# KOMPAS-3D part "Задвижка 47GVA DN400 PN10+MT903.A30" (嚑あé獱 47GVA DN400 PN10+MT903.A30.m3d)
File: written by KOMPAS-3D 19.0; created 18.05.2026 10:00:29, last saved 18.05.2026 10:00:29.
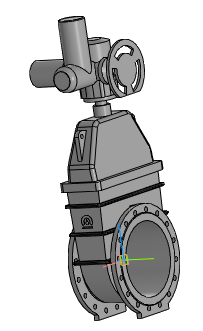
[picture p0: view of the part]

Document properties: Автор: Энергия; Полное имя файла: ..\Задвижка 47GVA DN50_DN1000+MT903.A\Задвижка 47GVA DN400 PN10+MT903.A30.a3d

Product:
- Part/product: Задвижка 47GVA DN400 PN10+MT903.A30
    Масса: 765.375
  - Body: Электропривод МТ903.А30 без блока управления
      Масса: 163.268
  - Body: Задвижка 47GVA DN400 PN10 без исполнительного механизма
      Масса: 602.107

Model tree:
1. Операция без истории:1
2. Операция без истории:2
